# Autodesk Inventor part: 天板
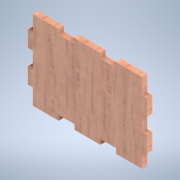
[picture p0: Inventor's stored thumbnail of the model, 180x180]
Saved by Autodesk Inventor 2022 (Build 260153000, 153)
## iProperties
Created: 2024-11
Part Number: 天板
Material: 木 (オーク)
Document SubType Name: Modeling
Designer: shimizu
Density: 0.76 g/cm^3
Appearance: ホワイト オーク材 - ナチュラル 標準の光沢
Author: shimizu
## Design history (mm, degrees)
sketch "スケッチ1"
  geometry: L1 (-25.119, 2.566)-(-27.619, 2.566); L2 (-27.619, 2.566)-(-27.619, -5.434); L3 (-27.619, -5.434)-(-25.119, -5.434); L4 (-25.119, -13.434)-(-27.619, -13.434); L5 (-27.619, -13.434)-(-27.619, -21.434); L6 (-27.619, -21.434)-(-25.119, -21.434); L7 (29.881, 2.566)-(32.381, 2.566); L8 (32.381, 2.566)-(32.381, -5.434); L9 (32.381, -5.434)-(29.881, -5.434); L10 (29.881, -13.434)-(32.381, -13.434); L11 (32.381, -13.434)-(32.381, -21.434); L12 (32.381, -21.434)-(29.881, -21.434); L13 (-25.119, 2.566)-(-25.119, 10.566); L14 (-25.119, -29.434)-(-25.119, -21.434); L15 (-25.119, -13.434)-(-25.119, -5.434); L16 (29.881, 10.566)-(29.881, 2.566); L17 (29.881, -5.434)-(29.881, -13.434); L18 (29.881, -21.434)-(29.881, -29.434); L19 (-4.119, -29.434)-(-4.119, -26.934); L20 (-4.119, -26.934)-(-12.119, -26.934); L21 (-12.119, -26.934)-(-12.119, -29.434); L22 (16.881, -29.434)-(16.881, -26.934); L23 (16.881, -26.934)-(8.881, -26.934); L24 (8.881, -26.934)-(8.881, -29.434); L25 (-4.119, 10.566)-(-4.119, 8.066); L26 (-4.119, 8.066)-(-12.119, 8.066); L27 (-12.119, 8.066)-(-12.119, 10.566); L28 (16.881, 10.566)-(16.881, 8.066); L29 (16.881, 8.066)-(8.881, 8.066); L30 (8.881, 8.066)-(8.881, 10.566); L31 (-25.119, 10.566)-(-12.119, 10.566); L32 (-4.119, 10.566)-(8.881, 10.566); L33 (16.881, 10.566)-(29.881, 10.566); L34 (-12.119, -29.434)-(-25.119, -29.434); L35 (29.881, -29.434)-(16.881, -29.434); L36 (8.881, -29.434)-(-4.119, -29.434); 1 further point
  constraints: 72 end point, 26 parallel, 13 perpendicular, 7 horizontal, 2 collinear
  dimensions: "d29" = 55 distance between parallel lines of L17 L15; "d30" = 35 distance between parallel lines of L20 L26; "d31" = 60 distance between parallel lines of L11 L5; "d32" = 13 distance of L21.end L14.start; "d33" = 13 distance of L24.end L19.start; "d34" = 13 distance of L18.end L22.start; "d35" = 13 distance of L13.end L27.end; "d36" = 13 distance of L25.start L30.end; "d37" = 13 distance of L28.start L16.start; "d38" = 8 distance of L28.end L29.end; "d39" = 8 distance of L25.end L26.end; "d40" = 8 distance of L22.end L23.end; "d41" = 8 distance of L19.end L20.end; "d42" = 8 distance of L9.end L10.start
extrude "押し出し1" new body sketch "スケッチ1" distance "d2" = 2.5; taper "d3" = 0 deg
node "ソリッド1"
